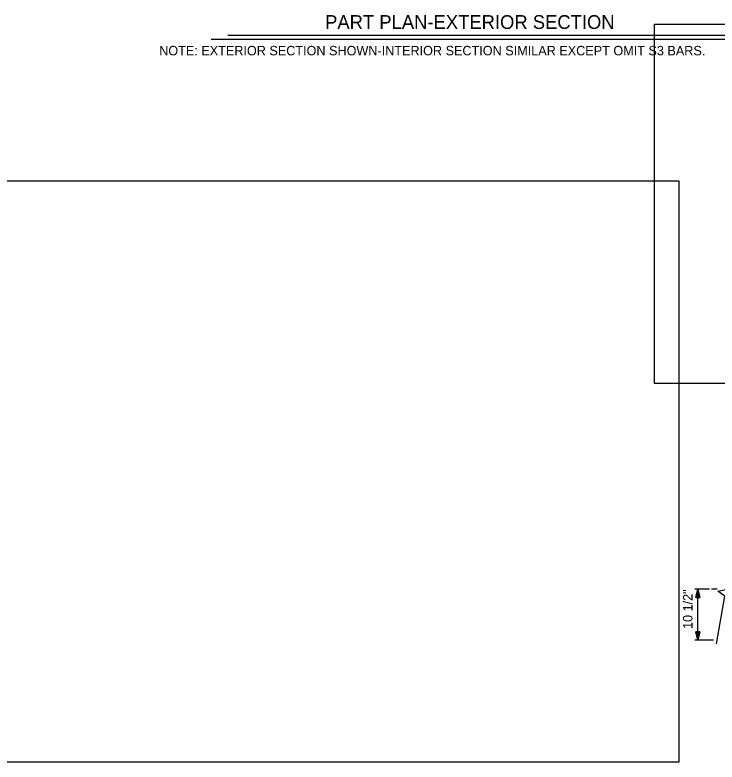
# Model space of a CAD drawing. Extents: x -408 to -23, y -15 to 117.
# Drawn here: x -349.43 to -338.8, y 20.08 to 31.39 of the extents above; entities that cross this region are included whole.
import ezdxf

# ---------------------------------------------------------------- set-up
doc = ezdxf.new("R2010")
doc.units = 0
for name, color, linetype in [('Dimension Lines', 7, 'Continuous'), ('Mis Center Lines', 7, 'Continuous'), ('Sup Concrete Girder Lines', 7, 'Continuous'), ('Text', 7, 'Continuous'), ('User Information Notes', 7, 'Continuous')]:
    doc.layers.add(name, color=color, linetype=linetype)

msp = doc.modelspace()

# ---------------------------------------------------------------- linework, layer by layer
at = {"layer": 'Dimension Lines'}
for p, q in [((-339.091, 21.925), (-339.091, 22.694)), ((-338.856, 21.925), (-339.138, 21.925))]:
    msp.add_line(p, q, dxfattribs=at)
for points in [[(-339.091, 22.569), (-339.097, 22.569), (-339.091, 22.694), (-339.103, 22.569), (-339.109, 22.569), (-339.091, 22.694), (-339.116, 22.569), (-339.122, 22.569), (-339.091, 22.694), (-339.059, 22.569), (-339.066, 22.569), (-339.091, 22.694), (-339.072, 22.569), (-339.078, 22.569), (-339.091, 22.694), (-339.084, 22.569), (-339.122, 22.569), (-339.059, 22.569), (-339.091, 22.694), (-339.122, 22.569)], [(-339.091, 22.05), (-339.084, 22.05), (-339.091, 21.925), (-339.078, 22.05), (-339.072, 22.05), (-339.091, 21.925), (-339.066, 22.05), (-339.059, 22.05), (-339.091, 21.925), (-339.122, 22.05), (-339.116, 22.05), (-339.091, 21.925), (-339.109, 22.05), (-339.103, 22.05), (-339.091, 21.925), (-339.097, 22.05), (-339.059, 22.05), (-339.122, 22.05), (-339.091, 21.925), (-339.059, 22.05)]]:
    msp.add_lwpolyline(points, dxfattribs=at)
at = {"layer": 'Mis Center Lines'}
for p, q in [((-338.916, 22.694), (-339.138, 22.694)), ((-338.801, 22.694), (-338.885, 22.694))]:
    msp.add_line(p, q, dxfattribs=at)
at = {"layer": 'Sup Concrete Girder Lines'}
msp.add_lwpolyline([(-338.81, 21.868), (-338.683, 22.589), (-338.791, 22.664), (-338.533, 22.722), (-338.647, 22.794), (-338.514, 23.546)], dxfattribs=at)
at = {"layer": 'Text'}
for p, q in [((-346.456, 31.018), (-342.297, 31.018)), ((-346.206, 31.081), (-342.297, 31.081)), ((-342.297, 31.081), (-338.389, 31.081)), ((-342.297, 31.018), (-338.139, 31.018))]:
    msp.add_line(p, q, dxfattribs=at)
at = {"layer": 'User Information Notes'}
for points in [[(-339.745, 31.249), (-329.877, 31.249), (-329.877, 25.809), (-339.745, 25.809)], [(-366.503, 28.874), (-339.381, 28.874), (-339.381, 20.079), (-366.503, 20.079)]]:
    msp.add_lwpolyline(points, close=True, dxfattribs=at)

# ---------------------------------------------------------------- texts
at = {"layer": 'Text'}
for s, height, p in [('PART PLAN-EXTERIOR SECTION', 0.20839, (-344.733, 31.175)), ('NOTE: EXTERIOR SECTION SHOWN-INTERIOR SECTION SIMILAR EXCEPT OMIT S3 BARS.', 0.143, (-347.244, 30.775))]:
    msp.add_text(s, height=height, dxfattribs=at).set_placement(p)
msp.add_text('10 1/2"', height=0.143, rotation=90, dxfattribs=at).set_placement((-339.172, 22.093))

doc.saveas('drawing.dxf')
